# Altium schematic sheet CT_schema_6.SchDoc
size 370 x 245 mm
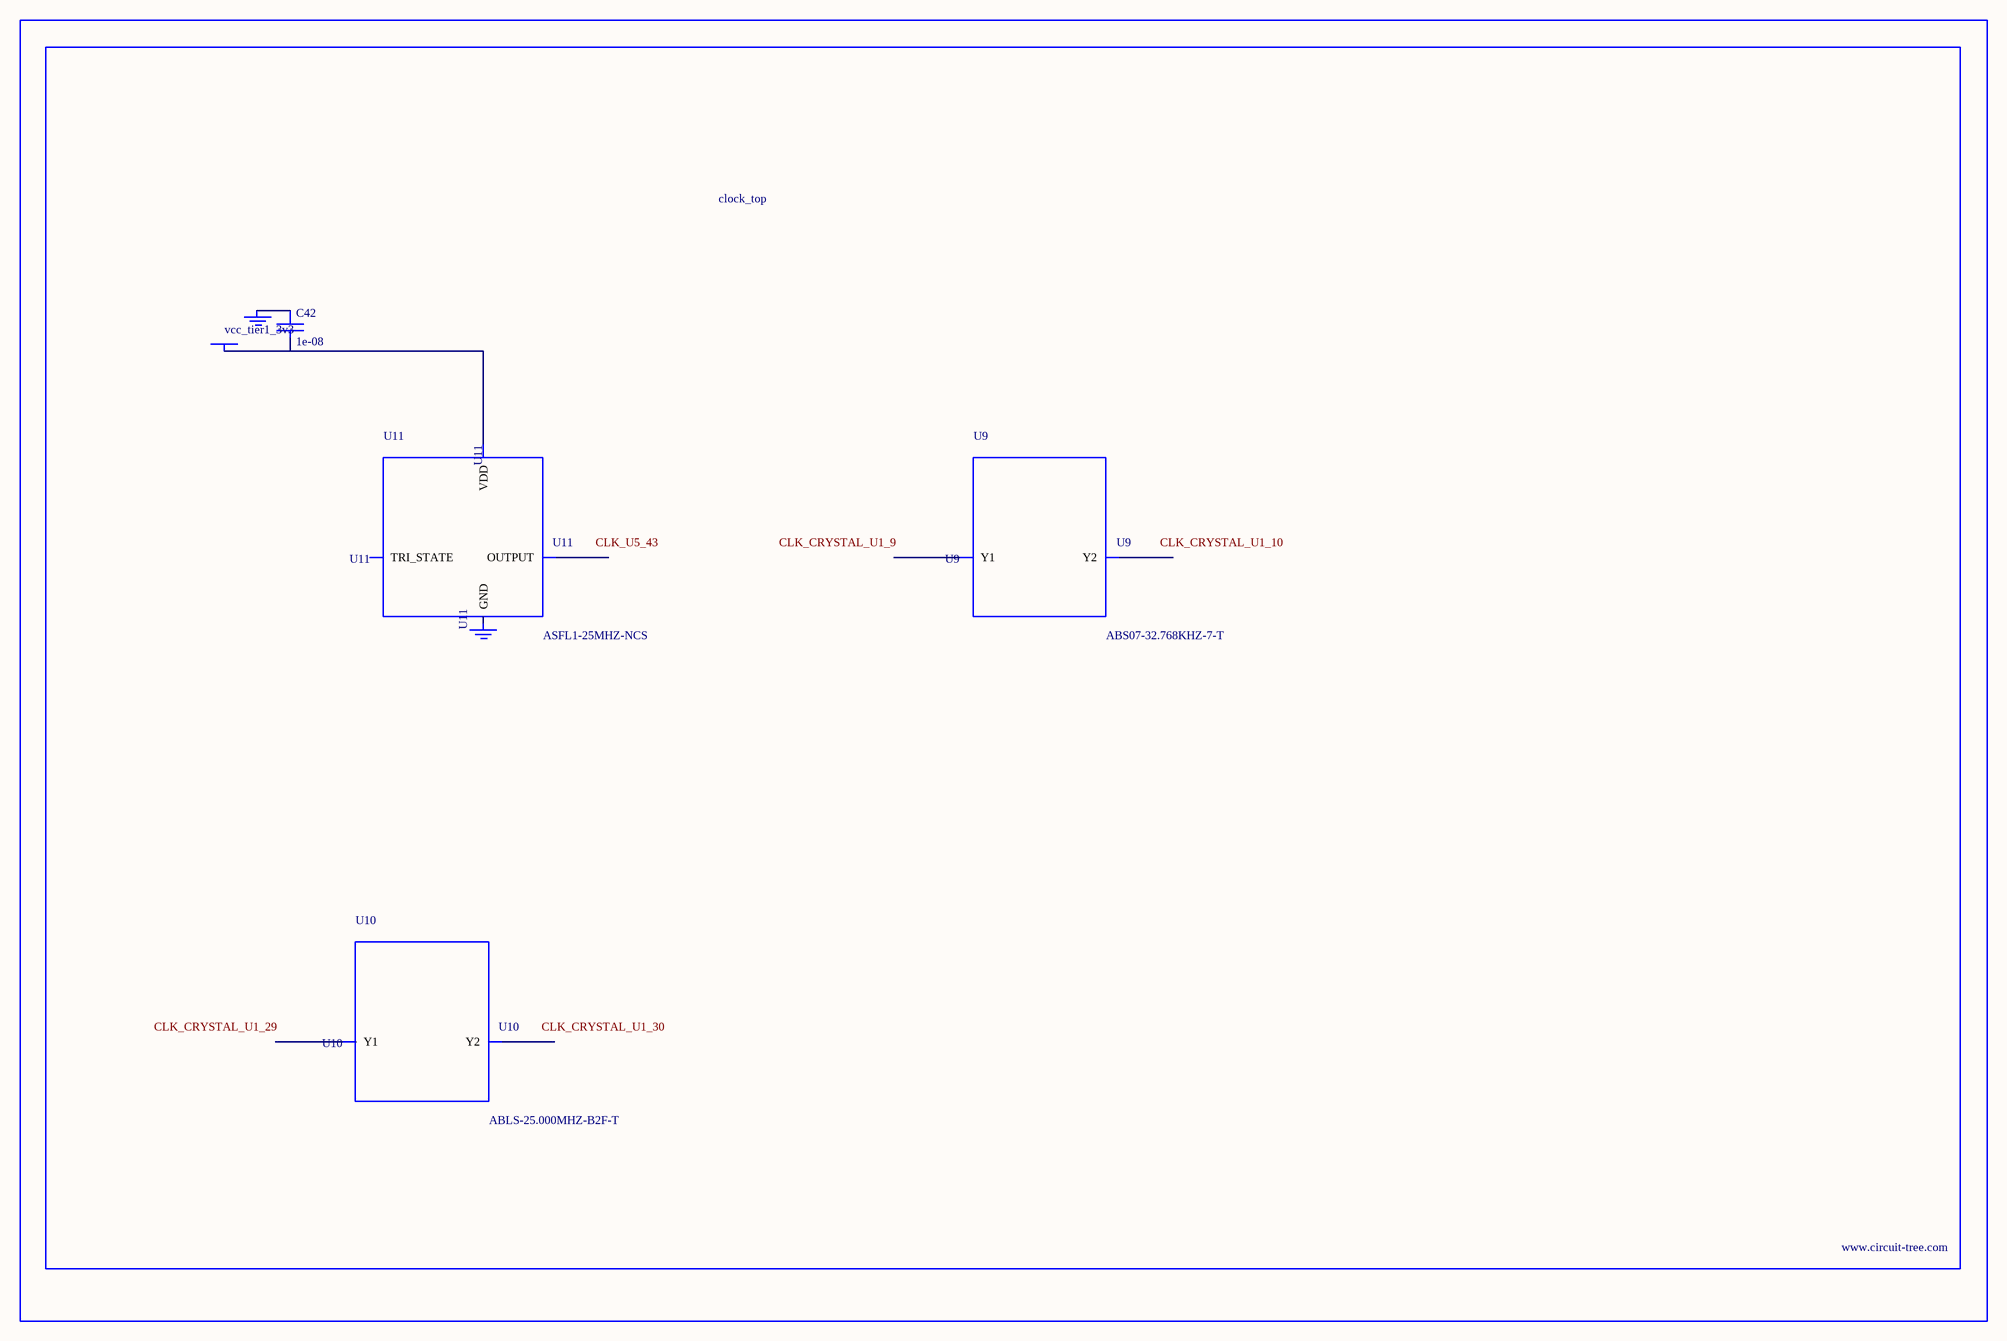
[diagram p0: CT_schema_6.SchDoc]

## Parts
BORDER5  (no value)
C42  1e-08  [C0402]
GND_INSTANCE_5_0  (no value)
GND_INSTANCE_5_1  (no value)
POWER_INSTANCE_5_0  vcc_tier1_3v3
U9  ABS07-32.768KHZ-7-T  [ABS07-32.768KHZ-7-T]
U10  ABLS-25.000MHZ-B2F-T  [ABLS-25.000MHZ-B2F-T]
U11  ASFL1-25MHZ-NCS  [ASFL1]

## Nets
NetC42_1: C42.1 GND_INSTANCE_5_0.0(GND)
NetC42_2: C42.2 POWER_INSTANCE_5_0.0(PWR) U11.4(VDD)

Not connected (* = marked no-connect by the designer): GND_INSTANCE_5_1 0(GND); U9 1(Y1) 2(Y2); U10 1(Y1) 2(Y2); U11 1(TRI_STATE) 2(GND) 3(OUTPUT)

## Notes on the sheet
- Labels drawn without touching a wire or pin: CLK_CRYSTAL_U1_9, CLK_CRYSTAL_U1_10, CLK_CRYSTAL_U1_29, CLK_CRYSTAL_U1_30, CLK_U5_43

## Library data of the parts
BORDER5 = BORDER_PAGE5
C42 = C0402C103K3RAC
GND_INSTANCE_5_0 GND_INSTANCE_5_1 = GND
POWER_INSTANCE_5_0 = PWR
